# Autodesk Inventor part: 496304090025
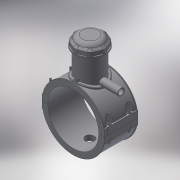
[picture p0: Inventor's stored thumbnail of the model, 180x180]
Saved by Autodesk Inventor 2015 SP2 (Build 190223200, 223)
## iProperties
Created: 2017-07
Part Number: 496304090025
Material: Generic
Description: PLASSON TAPPING SADDLE 90x25
Document SubType Name: Modeling
Designer: KIM
Mass: 575.119 g
Surface Area: 1460.7 cm^2
Volume: 575.119 cm^3
Density: 1 g/cm^3
Appearance: Default
Author: KIM
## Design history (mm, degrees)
derived "496304.ipt"
feature "Solid1::496304.ipt"
feature "Solid2::496304.ipt"
feature "Solid4::496304.ipt"
feature "Solid5::496304.ipt"
tag "TaggingFeature1"
body "Solid1"
body "Solid2"
other parameters: "d2" = 126, "d3" = 22.5, "d4" = 118, "d5" = 0, "d6" = 0.1, "d8" = 0, "d19" = 6, "d20" = 6, "d21" = 70.8, "d23" = 0, "d24" = 35.4, "d26" = 0, "d29" = 3, "d31" = 6, "d32" = 0, "d33" = 0, "d34" = 0.6, "d40" = 58.032, "d41" = 63, "d43" = 0, "d45" = 0, "d47" = 126.6, "d70" = 15, "d72" = 0, "d73" = 6, "d75" = 5, "d76" = 0, "d77" = 4.5, "d78" = 75, "d79" = 15, "d80" = 47.2, "d82" = 5 deg, "d84" = 4, "d85" = 14, "d86" = 0, "d87" = 3, "d88" = 0, "d89" = 1, "d90" = 1, "d91" = 94.4, "d92" = 0, "d93" = 0.5, "d94" = 47.36842, "d96" = 113.832, "d97" = 2.36, "d98" = 0, "d102" = 0.9, "d120" = 140 deg, "d121" = 24.228, "d122" = 20 deg, "d123" = 223.2, "d124" = 66.96, "d126" = 0, "d143" = 92.7, "d145" = 16.61538, "d149" = 1.35, "d150" = 18.27692, "d153" = 118, "d154" = 0, "d156" = 55.8, "d157" = 160 deg, "d159" = 4.32, "d161" = 1.35, "d162" = 70.8, "d163" = 0, "d164" = 45, "d167" = 9, "d168" = 54.43902, "d170" = 3.375, "d172" = 0, "d173" = 1, "d175" = 45, "d176" = 20 deg, "d177" = 6.3, "d178" = 21.6, "d180" = 0, "d183" = 8.64, "d184" = 5.04, "d185" = 38.35, "d186" = 38.35, "d187" = 55.8, "d188" = 6.48, "d189" = 6.3, "d190" = 0, "d191" = 83.7, "d193" = 6.3, "d194" = 4.13, "d195" = 90 deg, "d197" = 0, "d199" = 0, "d200" = 10.8, "d202" = 0, "d203" = 114, "d204" = 59.85, "d205" = 44.1, "d206" = 53.55, "d207" = 85.5, "d208" = 88.92, "d209" = 106.02, "d210" = 54.18, "d211" = 63, "d212" = 50.4, "d213" = 3.15, "d216" = 0, "d217" = 9, "d218" = 9, "d219" = 1.8, "d224" = 0, "d230" = 5.4, "d233" = 6, "d236" = 63, "d237" = 35.4, "d238" = 6.02433, "d240" = 35.4, "d241" = 35.4, "d242" = 35.4, "d243" = 6, "d244" = 35.4, "d245" = 35.4, "d246" = 35.4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
